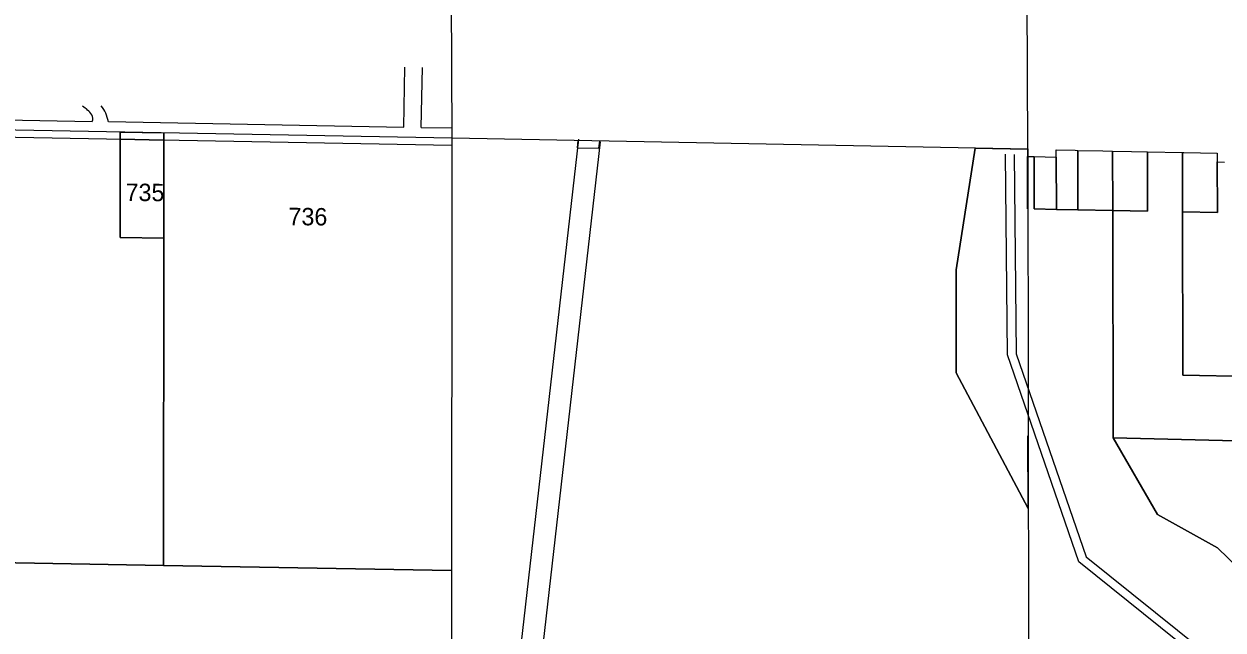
# Model space of a CAD drawing. Extents: x 582596 to 627039, y 145946 to 197316.
# Drawn here: x 610608 to 616103, y 167820 to 170596 of the extents above; entities that cross this region are included whole.
import ezdxf

# ---------------------------------------------------------------- set-up
doc = ezdxf.new("R2010")
doc.units = 0
for name, color, linetype in [('Defpoints 2', 7, 'Continuous'), ('E_RW_EasementUtility', 7, 'Continuous'), ('E_RW_Existing', 7, 'Continuous'), ('P_RW_PropertyLine', 7, 'Continuous'), ('P_RW_QuarterLine', 7, 'Continuous'), ('P_RW_SectionLine', 7, 'Continuous')]:
    doc.layers.add(name, color=color, linetype=linetype)

msp = doc.modelspace()

# ---------------------------------------------------------------- linework, layer by layer
at = {"layer": 'E_RW_EasementUtility'}
for points in [[(615782, 164967.6), (615831.2, 165721.9), (615831, 166539.8), (616025.7, 167280.4), (615965.4, 167713.3), (615441.9, 168132.8), (615114.9, 169080.1), (615105.8, 170000.3)], [(615145.8, 169999), (615154.8, 169085.4), (615476, 168155.1), (616002.8, 167732.8), (616066.4, 167276.3), (615871, 166533), (615871.2, 165718.9), (615822.1, 164966.9)]]:
    msp.add_lwpolyline(points, dxfattribs=at)
at = {"layer": 'E_RW_Existing'}
for p, q in [((612349, 170124), (612354.1, 170398.5)), ((612429, 170122.5), (612434.1, 170397.1)), ((609964.7, 170089.6), (612569.6, 170041.9))]:
    msp.add_line(p, q, dxfattribs=at)
for points in [[(610360.7, 170148.4), (610360.6, 170160.4), (610921.1, 170150.1)], [(610995.2, 170148.8), (612349, 170124)], [(612429, 170122.5), (612571, 170119.9)]]:
    msp.add_lwpolyline(points, dxfattribs=at)
for centre, radius, start, end in [((610818.7, 170113.8), 120, 33.3686, 61.4393), ((610896.2, 170163.2), 28.1, 332.2653, 36.1823), ((610818.9, 170114), 179.7, 11.1503, 36.8765)]:
    msp.add_arc(centre, radius, start, end, dxfattribs=at)
at = {"layer": 'P_RW_PropertyLine'}
for p, q in [((611049.7, 170068.3), (611049.1, 169618.3)), ((611049.1, 169618.3), (611049.7, 170068.3)), ((611049.7, 170101.3), (611049.7, 170068.3)), ((611049.7, 170068.3), (611049.7, 170101.3)), ((611049.7, 170101.3), (611249.6, 170097.6)), ((611049.7, 170068.3), (611249.6, 170064.6)), ((611249.6, 170064.6), (611049.7, 170068.3)), ((611249, 169614.6), (611249.6, 170064.6)), ((611249.6, 170064.6), (611249, 169614.6)), ((611249.6, 170064.6), (611249.6, 170097.6)), ((611249.6, 170097.6), (611249.6, 170064.6)), ((613149.4, 170068.4), (612547.1, 164789.5)), ((613248.8, 170057), (612647.5, 164787.2)), ((613146.9, 170062.1), (613142.9, 170029.2)), ((613142.9, 170029.2), (613243.3, 170027.3)), ((613243.3, 170027.3), (613247.4, 170060.2)), ((614967.2, 170026.7), (614880, 169470.5)), ((614880, 169470.5), (614967.2, 170026.7)), ((614967.2, 170026.7), (615207.2, 170022.1)), ((615207.2, 170022.1), (615207.2, 169989.1)), ((615339.2, 169986.4), (615339.2, 170019.4)), ((615339.2, 170019.4), (615426.2, 170017.7)), ((615426.2, 170017.7), (615437.2, 170017.4)), ((615437.2, 170017.4), (615437.6, 169745.2)), ((615437.6, 169745.2), (615437.2, 170017.4)), ((615437.2, 170017.4), (615553.1, 170015.1)), ((615553.1, 170015.1), (615597.1, 170014.2)), ((615597.1, 170014.2), (615597.5, 169742)), ((615597.5, 169742), (615597.1, 170014.2)), ((615597.1, 170014.2), (615683.1, 170012.5)), ((615683.1, 170012.5), (615757.1, 170011)), ((615757.1, 170011), (615757.5, 169738.7)), ((615757.5, 169738.7), (615757.1, 170011)), ((615757.1, 170011), (615917.1, 170007.8)), ((615207.2, 169989.1), (615207.6, 169749.8)), ((615207.6, 169749.8), (615207.2, 169989.1)), ((615207.2, 169989.1), (615237.2, 169988.5)), ((615237.6, 169749.9), (615237.2, 169988.5)), ((615237.2, 169988.5), (615339.2, 169986.4)), ((615237.2, 169988.5), (615237.6, 169749.9)), ((615339.6, 169747.2), (615339.2, 169986.4)), ((615339.2, 169986.4), (615339.6, 169747.2)), ((615917.5, 169735.5), (615917.1, 170007.8)), ((615917.1, 170007.8), (615923.3, 170007.7)), ((615917.1, 170007.8), (615917.5, 169735.5)), ((615923.3, 170007.7), (616077, 170004.6)), ((616077, 170004.6), (616077.1, 169964.5)), ((616077.4, 169732.3), (616077.1, 169964.5)), ((616077.1, 169964.5), (616110, 169963.9)), ((616077.1, 169964.5), (616077.4, 169732.3)), ((615237.4, 169749.2), (615237.6, 169749.9)), ((615237.6, 169749.9), (615237.4, 169749.2)), ((615237.6, 169749.2), (615237.4, 169749.2)), ((615237.4, 169749.2), (615237.6, 169749.2)), ((615339.6, 169747.2), (615237.6, 169749.2)), ((615237.6, 169749.2), (615339.6, 169747.2)), ((615437.6, 169745.2), (615339.6, 169747.2)), ((615339.6, 169747.2), (615437.6, 169745.2)), ((615437.6, 169745.2), (615597.5, 169742)), ((615597.5, 169742), (615437.6, 169745.2)), ((615597.5, 169742), (615599.1, 168700.1)), ((615757.5, 169738.7), (615597.5, 169742)), ((615599.1, 168700.1), (615597.5, 169742)), ((615597.5, 169742), (615757.5, 169738.7)), ((615918.6, 168987.7), (615917.5, 169735.5)), ((615917.5, 169735.5), (616077.4, 169732.3)), ((616077.4, 169732.3), (615917.5, 169735.5)), ((615917.5, 169735.5), (615918.6, 168987.7)), ((611049.1, 169618.3), (611249, 169614.6)), ((611249, 169614.6), (611049.1, 169618.3)), ((611247.1, 168116.3), (611249, 169614.6)), ((611249, 169614.6), (611247.1, 168116.3)), ((614880, 169470.5), (614880.7, 168998.5)), ((614880.7, 168998.5), (614880, 169470.5)), ((614880.7, 168998.5), (615209.6, 168377)), ((615209.6, 168377), (614880.7, 168998.5)), ((616527.6, 168975.5), (615918.6, 168987.7)), ((615918.6, 168987.7), (616527.6, 168975.5)), ((615209.1, 168709.7), (615209.6, 168377)), ((615209.6, 168377), (615209.1, 168709.7)), ((615599.1, 168700.1), (615803, 168350.2)), ((616527.9, 168677.2), (615599.1, 168700.1)), ((615803, 168350.2), (615599.1, 168700.1)), ((615599.1, 168700.1), (616527.9, 168677.2)), ((615803, 168350.2), (616078, 168196.6)), ((616078, 168196.6), (615803, 168350.2)), ((616078, 168196.6), (616397.2, 167886.6)), ((616397.2, 167886.6), (616078, 168196.6)), ((611247.1, 168116.3), (609959.6, 168138.7)), ((609959.6, 168138.7), (611247.1, 168116.3)), ((612567.5, 168093.4), (611247.1, 168116.3)), ((611247.1, 168116.3), (612567.5, 168093.4))]:
    msp.add_line(p, q, dxfattribs=at)
at = {"layer": 'P_RW_QuarterLine'}
for p, q in [((612570.2, 170074.9), (612559.2, 172723.7)), ((612568.2, 167435), (612570.2, 170074.9))]:
    msp.add_line(p, q, dxfattribs=at)
at = {"layer": 'P_RW_SectionLine'}
for p, q in [((615208.5, 170023.6), (615198.6, 172667.7)), ((609931.7, 170123.2), (612570.2, 170074.9)), ((612570.2, 170074.9), (615208.5, 170023.6)), ((615208.5, 170023.6), (615212.2, 167389))]:
    msp.add_line(p, q, dxfattribs=at)

# ---------------------------------------------------------------- texts
at = {"layer": 'Defpoints 2'}
for s, p in [('735', (611073.8, 169785.7)), ('736', (611820.4, 169674.8))]:
    msp.add_text(s, height=79.68, rotation=359.5042, dxfattribs=at).set_placement(p)

doc.saveas('drawing.dxf')
